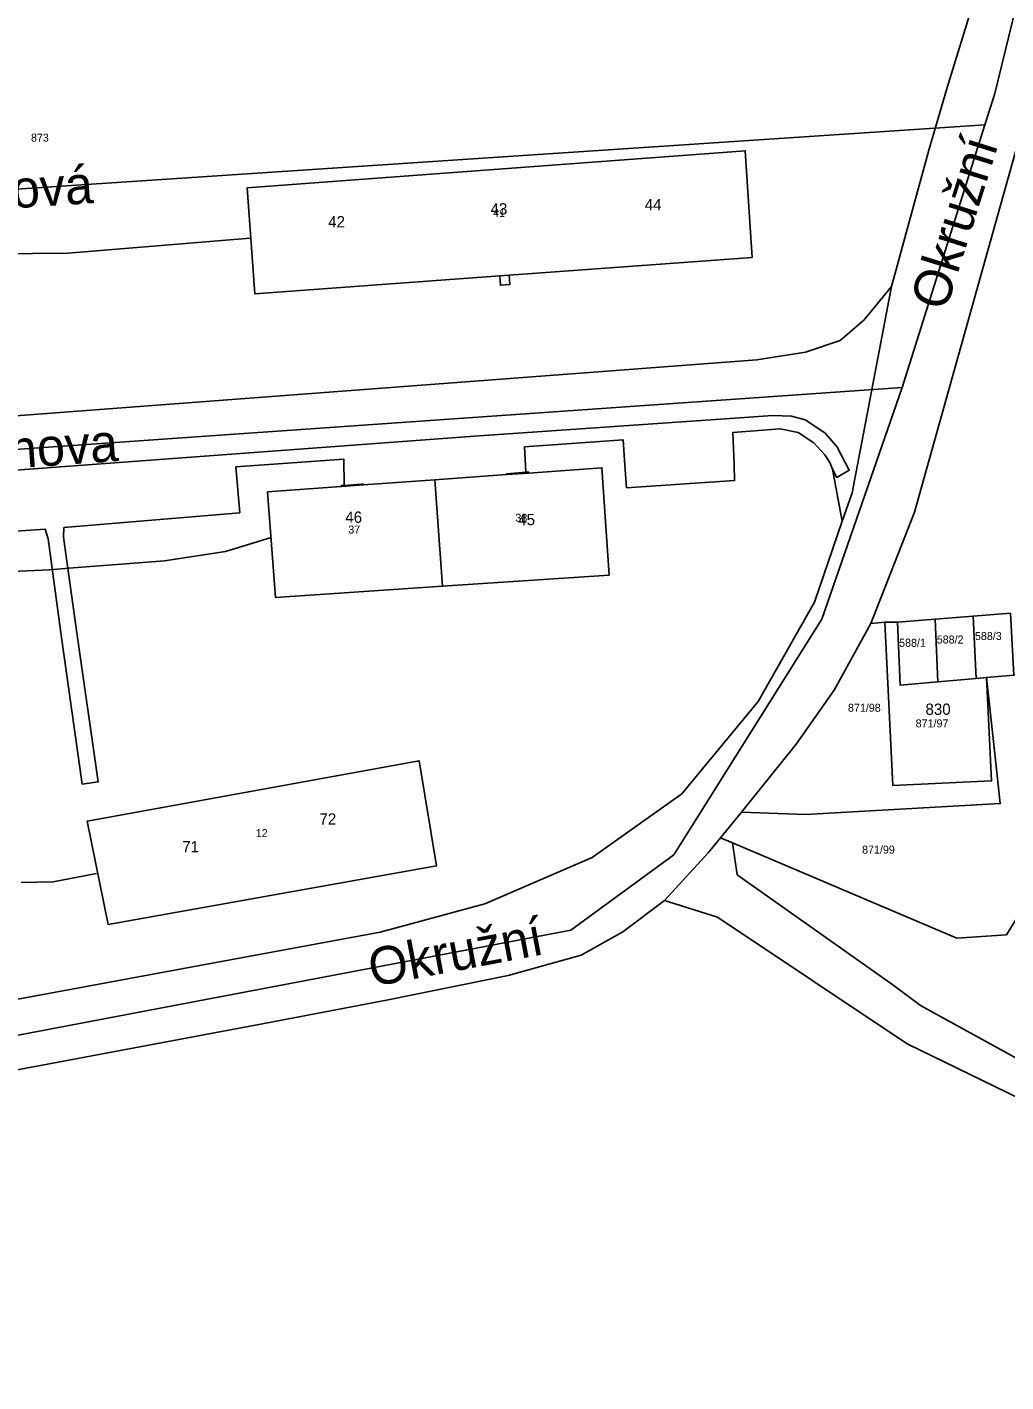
# Model space of a CAD drawing. Extents: x -873642 to -872917, y -1012962 to -1012567.
# Drawn here: x -873173.4 to -873069.4, y -1012787.3 to -1012643.4 of the extents above; entities that cross this region are included whole.
import ezdxf

# ---------------------------------------------------------------- set-up
doc = ezdxf.new("R2010")
doc.units = 0
for name, color, linetype in [('adresni_misto', 7, 'Continuous'), ('cisla_parcelni_kn', 7, 'Continuous'), ('cislo_domovni', 7, 'Continuous'), ('osy_ulic', 7, 'Continuous'), ('parcely_kn', 7, 'Continuous'), ('stavebni_objekty_bydleni', 7, 'Continuous'), ('stavebni_objekty_ostatni', 7, 'Continuous'), ('TRASY - zamereno', 7, 'Continuous'), ('ulice', 7, 'Continuous')]:
    doc.layers.add(name, color=color, linetype=linetype)

msp = doc.modelspace()

# ---------------------------------------------------------------- linework, layer by layer
at = {"layer": 'adresni_misto'}
for p, q in [((-873123.13, -1012664.19), (-873123.13, -1012664.19)), ((-873106.75, -1012663.75), (-873106.75, -1012663.75)), ((-873140.38, -1012665.56), (-873140.38, -1012665.56)), ((-873138.56, -1012696.94), (-873138.56, -1012696.94)), ((-873120.19, -1012697.19), (-873120.19, -1012697.19)), ((-873076.33, -1012717.34), (-873076.33, -1012717.34)), ((-873141.31, -1012729), (-873141.31, -1012729)), ((-873155.88, -1012731.94), (-873155.88, -1012731.94))]:
    msp.add_line(p, q, dxfattribs=at)
at = {"layer": 'osy_ulic'}
for points in [[(-873411.85, -1012822.53), (-873317.85, -1012788.44), (-873277.23, -1012773.91), (-873252.76, -1012767.01), (-873201.18, -1012755.57), (-873115.6, -1012739.3), (-873104.65, -1012731.3), (-873088.93, -1012706.26), (-873080.41, -1012681.66), (-873071.61, -1012653.78), (-873070.57, -1012650.45), (-873066.08, -1012632.13), (-873063.74, -1012625.63), (-873059.56, -1012597.3)], [(-873071.61, -1012653.78), (-873259.84, -1012666.28), (-873257.79, -1012694.05)], [(-873471.18, -1012707.47), (-873461.09, -1012708.93), (-873257.79, -1012694.05), (-873080.41, -1012681.66)]]:
    msp.add_lwpolyline(points, dxfattribs=at)
at = {"layer": 'parcely_kn'}
for points in [[(-873079.43, -1012607.12), (-873054.9, -1012604.66), (-873052.37, -1012604.41), (-873054.28, -1012608.24), (-873059.76, -1012619.22), (-873058.34, -1012622.19), (-873062.75, -1012637.7), (-873065.7, -1012641.7), (-873065.38, -1012647.07), (-873066.31, -1012649.31), (-873079.09, -1012694.9), (-873083.74, -1012706.73), (-873087.64, -1012713.81), (-873091.65, -1012719.56), (-873097.47, -1012726.79), (-873099.7, -1012729.49), (-873101.03, -1012731.11), (-873105.65, -1012736.17), (-873110.07, -1012739.5), (-873114.5, -1012741.96), (-873122.26, -1012744.11), (-873135.01, -1012746.72), (-873148.18, -1012749.22), (-873185.58, -1012756.25)], [(-873079.43, -1012607.12), (-873054.9, -1012604.66), (-873052.37, -1012604.41), (-873054.28, -1012608.24), (-873059.76, -1012619.22), (-873058.34, -1012622.19), (-873062.75, -1012637.7), (-873065.7, -1012641.7), (-873065.38, -1012647.07), (-873066.31, -1012649.31), (-873079.09, -1012694.9), (-873083.74, -1012706.73), (-873087.64, -1012713.81), (-873091.65, -1012719.56), (-873097.47, -1012726.79), (-873099.7, -1012729.49), (-873101.03, -1012731.11), (-873105.65, -1012736.17), (-873110.07, -1012739.5), (-873114.5, -1012741.96), (-873122.26, -1012744.11), (-873135.01, -1012746.72), (-873148.18, -1012749.22), (-873185.58, -1012756.25)], [(-873320.46, -1012784.28), (-873268.07, -1012767.54), (-873249.92, -1012762.57), (-873226.73, -1012756.94), (-873186.64, -1012748.89), (-873149.68, -1012742.06), (-873135.84, -1012739.52), (-873124.72, -1012736.51), (-873113.32, -1012731.6), (-873103.81, -1012724.84), (-873095.71, -1012715.02), (-873089.72, -1012704.46), (-873086.77, -1012695.86), (-873085.73, -1012692.85), (-873081.52, -1012670.94), (-873077.58, -1012656.47), (-873075.63, -1012649.79), (-873072.81, -1012640.75), (-873068.46, -1012627.76), (-873067.09, -1012621.71)], [(-873320.46, -1012784.28), (-873268.07, -1012767.54), (-873249.92, -1012762.57), (-873226.73, -1012756.94), (-873186.64, -1012748.89), (-873149.68, -1012742.06), (-873135.84, -1012739.52), (-873124.72, -1012736.51), (-873113.32, -1012731.6), (-873103.81, -1012724.84), (-873095.71, -1012715.02), (-873089.72, -1012704.46), (-873086.77, -1012695.86), (-873085.73, -1012692.85), (-873081.52, -1012670.94), (-873077.58, -1012656.47), (-873075.63, -1012649.79), (-873072.81, -1012640.75), (-873068.46, -1012627.76), (-873067.09, -1012621.71)], [(-873067.09, -1012621.71), (-873068.46, -1012627.76), (-873072.81, -1012640.75), (-873075.63, -1012649.79), (-873077.58, -1012656.47), (-873081.52, -1012670.94), (-873084.44, -1012674.48), (-873086.98, -1012676.69), (-873090.68, -1012677.91), (-873095.85, -1012678.72), (-873263.61, -1012691.39)], [(-873067.09, -1012621.71), (-873068.46, -1012627.76), (-873072.81, -1012640.75), (-873075.63, -1012649.79), (-873077.58, -1012656.47), (-873081.52, -1012670.94), (-873084.44, -1012674.48), (-873086.98, -1012676.69), (-873090.68, -1012677.91), (-873095.85, -1012678.72), (-873263.61, -1012691.39)], [(-873068.89, -1012705.62), (-873072.87, -1012705.95), (-873076.91, -1012706.28), (-873080.89, -1012706.61), (-873082.23, -1012706.6), (-873083.74, -1012706.73), (-873079.09, -1012694.9), (-873066.31, -1012649.31)], [(-873068.89, -1012705.62), (-873072.87, -1012705.95), (-873076.91, -1012706.28), (-873080.89, -1012706.61), (-873082.23, -1012706.6), (-873083.74, -1012706.73), (-873079.09, -1012694.9), (-873066.31, -1012649.31)], [(-873263.61, -1012691.39), (-873095.85, -1012678.72), (-873090.68, -1012677.91), (-873086.98, -1012676.69), (-873084.44, -1012674.48), (-873081.52, -1012670.94), (-873085.73, -1012692.85), (-873086.77, -1012695.86), (-873087.8, -1012690.33), (-873087.35, -1012691.21), (-873086.02, -1012690.46), (-873087.36, -1012687.92), (-873088.63, -1012686.48), (-873090.71, -1012685.11), (-873092.16, -1012684.7), (-873094.19, -1012684.63), (-873097.17, -1012684.84), (-873125.83, -1012686.85), (-873192.31, -1012691.74)], [(-873263.61, -1012691.39), (-873095.85, -1012678.72), (-873090.68, -1012677.91), (-873086.98, -1012676.69), (-873084.44, -1012674.48), (-873081.52, -1012670.94), (-873085.73, -1012692.85), (-873086.77, -1012695.86), (-873087.8, -1012690.33), (-873087.35, -1012691.21), (-873086.02, -1012690.46), (-873087.36, -1012687.92), (-873088.63, -1012686.48), (-873090.71, -1012685.11), (-873092.16, -1012684.7), (-873094.19, -1012684.63), (-873097.17, -1012684.84), (-873125.83, -1012686.85), (-873192.31, -1012691.74)], [(-873192.31, -1012691.74), (-873125.83, -1012686.85), (-873097.17, -1012684.84), (-873094.19, -1012684.63), (-873092.16, -1012684.7), (-873090.71, -1012685.11), (-873088.63, -1012686.48), (-873087.36, -1012687.92), (-873086.02, -1012690.46), (-873087.35, -1012691.21), (-873087.8, -1012690.33), (-873088.09, -1012689.62), (-873088.61, -1012688.81), (-873089.78, -1012687.56), (-873091.46, -1012686.44), (-873093.35, -1012686.07), (-873098.39, -1012686.43), (-873098.26, -1012689.84), (-873098.2, -1012691.55), (-873109.68, -1012692.31), (-873109.85, -1012689.9), (-873110.04, -1012687.24), (-873120.52, -1012687.97), (-873120.37, -1012690.67), (-873121.97, -1012690.79), (-873122.43, -1012690.82), (-873122.43, -1012690.92), (-873130.05, -1012691.47), (-873137.64, -1012692.02), (-873137.65, -1012691.92), (-873137.83, -1012691.93), (-873139.68, -1012692.07), (-873139.71, -1012689.29), (-873151.19, -1012690.1), (-873150.77, -1012694.97), (-873169.45, -1012696.55), (-873169.48, -1012697.55), (-873168.1, -1012707.49), (-873165.81, -1012723.57), (-873167.5, -1012723.8), (-873169.77, -1012707.72), (-873171.13, -1012697.75), (-873171.45, -1012696.71), (-873178.09, -1012697.19)], [(-873192.31, -1012691.74), (-873125.83, -1012686.85), (-873097.17, -1012684.84), (-873094.19, -1012684.63), (-873092.16, -1012684.7), (-873090.71, -1012685.11), (-873088.63, -1012686.48), (-873087.36, -1012687.92), (-873086.02, -1012690.46), (-873087.35, -1012691.21), (-873087.8, -1012690.33), (-873088.09, -1012689.62), (-873088.61, -1012688.81), (-873089.78, -1012687.56), (-873091.46, -1012686.44), (-873093.35, -1012686.07), (-873098.39, -1012686.43), (-873098.26, -1012689.84), (-873098.2, -1012691.55), (-873109.68, -1012692.31), (-873109.85, -1012689.9), (-873110.04, -1012687.24), (-873120.52, -1012687.97), (-873120.37, -1012690.67), (-873121.97, -1012690.79), (-873122.43, -1012690.82), (-873122.43, -1012690.92), (-873130.05, -1012691.47), (-873137.64, -1012692.02), (-873137.65, -1012691.92), (-873137.83, -1012691.93), (-873139.68, -1012692.07), (-873139.71, -1012689.29), (-873151.19, -1012690.1), (-873150.77, -1012694.97), (-873169.45, -1012696.55), (-873169.48, -1012697.55), (-873168.1, -1012707.49), (-873165.81, -1012723.57), (-873167.5, -1012723.8), (-873169.77, -1012707.72), (-873171.13, -1012697.75), (-873171.45, -1012696.71), (-873178.09, -1012697.19)], [(-873178.09, -1012697.19), (-873171.45, -1012696.71), (-873171.13, -1012697.75), (-873169.77, -1012707.72), (-873167.5, -1012723.8), (-873165.81, -1012723.57), (-873168.1, -1012707.49), (-873169.48, -1012697.55), (-873169.45, -1012696.55), (-873150.77, -1012694.97), (-873151.19, -1012690.1), (-873139.71, -1012689.29), (-873139.68, -1012692.07), (-873139.99, -1012692.09), (-873139.99, -1012692.19), (-873147.82, -1012692.75), (-873146.96, -1012703.97), (-873129.24, -1012702.78), (-873111.54, -1012701.6), (-873112.3, -1012690.19), (-873120.08, -1012690.75), (-873120.09, -1012690.65), (-873120.37, -1012690.67), (-873120.52, -1012687.97), (-873110.04, -1012687.24), (-873109.85, -1012689.9), (-873109.68, -1012692.31), (-873098.2, -1012691.55), (-873098.26, -1012689.84), (-873098.39, -1012686.43), (-873093.35, -1012686.07), (-873091.46, -1012686.44), (-873089.78, -1012687.56), (-873088.61, -1012688.81), (-873088.09, -1012689.62), (-873087.8, -1012690.33), (-873086.77, -1012695.86), (-873089.72, -1012704.46), (-873095.71, -1012715.02), (-873103.81, -1012724.84), (-873113.32, -1012731.6), (-873124.72, -1012736.51), (-873135.84, -1012739.52), (-873149.68, -1012742.06), (-873186.64, -1012748.89)], [(-873178.09, -1012697.19), (-873171.45, -1012696.71), (-873171.13, -1012697.75), (-873169.77, -1012707.72), (-873167.5, -1012723.8), (-873165.81, -1012723.57), (-873168.1, -1012707.49), (-873169.48, -1012697.55), (-873169.45, -1012696.55), (-873150.77, -1012694.97), (-873151.19, -1012690.1), (-873139.71, -1012689.29), (-873139.68, -1012692.07), (-873139.99, -1012692.09), (-873139.99, -1012692.19), (-873147.82, -1012692.75), (-873146.96, -1012703.97), (-873129.24, -1012702.78), (-873111.54, -1012701.6), (-873112.3, -1012690.19), (-873120.08, -1012690.75), (-873120.09, -1012690.65), (-873120.37, -1012690.67), (-873120.52, -1012687.97), (-873110.04, -1012687.24), (-873109.85, -1012689.9), (-873109.68, -1012692.31), (-873098.2, -1012691.55), (-873098.26, -1012689.84), (-873098.39, -1012686.43), (-873093.35, -1012686.07), (-873091.46, -1012686.44), (-873089.78, -1012687.56), (-873088.61, -1012688.81), (-873088.09, -1012689.62), (-873087.8, -1012690.33), (-873086.77, -1012695.86), (-873089.72, -1012704.46), (-873095.71, -1012715.02), (-873103.81, -1012724.84), (-873113.32, -1012731.6), (-873124.72, -1012736.51), (-873135.84, -1012739.52), (-873149.68, -1012742.06), (-873186.64, -1012748.89)], [(-872958.67, -1012787.72), (-872975.04, -1012782.47), (-872991.42, -1012777.17), (-873018.29, -1012770.78), (-873034.35, -1012766.02), (-873054.3, -1012761.9), (-873065.25, -1012758.5), (-873079.89, -1012751.4), (-873100.03, -1012737.92), (-873105.65, -1012736.17), (-873101.03, -1012731.11), (-873099.7, -1012729.49), (-873098.43, -1012730.03), (-873097.94, -1012733.42), (-873081.4, -1012745.11), (-873078.44, -1012747.33), (-873067.46, -1012753.38), (-873059.91, -1012755.24), (-873032.7, -1012762.55), (-873015.14, -1012768.05), (-872991.17, -1012772.9), (-872969.11, -1012779.09), (-872954.48, -1012785.31), (-872943.22, -1012794.81)], [(-872958.67, -1012787.72), (-872975.04, -1012782.47), (-872991.42, -1012777.17), (-873018.29, -1012770.78), (-873034.35, -1012766.02), (-873054.3, -1012761.9), (-873065.25, -1012758.5), (-873079.89, -1012751.4), (-873100.03, -1012737.92), (-873105.65, -1012736.17), (-873101.03, -1012731.11), (-873099.7, -1012729.49), (-873098.43, -1012730.03), (-873097.94, -1012733.42), (-873081.4, -1012745.11), (-873078.44, -1012747.33), (-873067.46, -1012753.38), (-873059.91, -1012755.24), (-873032.7, -1012762.55), (-873015.14, -1012768.05), (-872991.17, -1012772.9), (-872969.11, -1012779.09), (-872954.48, -1012785.31), (-872943.22, -1012794.81)], [(-873067.46, -1012753.38), (-873078.44, -1012747.33), (-873081.4, -1012745.11), (-873097.94, -1012733.42), (-873098.43, -1012730.03), (-873074.59, -1012740.17), (-873069.33, -1012739.79)], [(-873067.46, -1012753.38), (-873078.44, -1012747.33), (-873081.4, -1012745.11), (-873097.94, -1012733.42), (-873098.43, -1012730.03), (-873074.59, -1012740.17), (-873069.33, -1012739.79)], [(-873185.58, -1012756.25), (-873148.18, -1012749.22), (-873135.01, -1012746.72), (-873122.26, -1012744.11), (-873114.5, -1012741.96), (-873110.07, -1012739.5), (-873105.65, -1012736.17), (-873100.03, -1012737.92), (-873079.89, -1012751.4), (-873065.25, -1012758.5), (-873054.3, -1012761.9), (-873034.35, -1012766.02), (-873018.29, -1012770.78), (-872991.42, -1012777.17), (-872975.04, -1012782.47), (-872958.67, -1012787.72)], [(-873185.58, -1012756.25), (-873148.18, -1012749.22), (-873135.01, -1012746.72), (-873122.26, -1012744.11), (-873114.5, -1012741.96), (-873110.07, -1012739.5), (-873105.65, -1012736.17), (-873100.03, -1012737.92), (-873079.89, -1012751.4), (-873065.25, -1012758.5), (-873054.3, -1012761.9), (-873034.35, -1012766.02), (-873018.29, -1012770.78), (-872991.42, -1012777.17), (-872975.04, -1012782.47), (-872958.67, -1012787.72)]]:
    msp.add_lwpolyline(points, dxfattribs=at)
for points in [[(-873150, -1012660.46), (-873149.18, -1012671.71), (-873123.16, -1012669.81), (-873123.09, -1012670.81), (-873122.09, -1012670.73), (-873122.17, -1012669.74), (-873096.35, -1012667.85), (-873097.08, -1012656.52)], [(-873150, -1012660.46), (-873097.08, -1012656.52), (-873096.35, -1012667.85), (-873122.17, -1012669.74), (-873122.09, -1012670.73), (-873123.09, -1012670.81), (-873123.16, -1012669.81), (-873149.18, -1012671.71)], [(-873150, -1012660.46), (-873149.18, -1012671.71), (-873123.16, -1012669.81), (-873123.09, -1012670.81), (-873122.09, -1012670.73), (-873122.17, -1012669.74), (-873096.35, -1012667.85), (-873097.08, -1012656.52)], [(-873150, -1012660.46), (-873097.08, -1012656.52), (-873096.35, -1012667.85), (-873122.17, -1012669.74), (-873122.09, -1012670.73), (-873123.09, -1012670.81), (-873123.16, -1012669.81), (-873149.18, -1012671.71)], [(-873120.08, -1012690.75), (-873112.3, -1012690.19), (-873111.54, -1012701.6), (-873129.24, -1012702.78), (-873130.05, -1012691.47), (-873122.43, -1012690.92), (-873122.43, -1012690.82), (-873121.97, -1012690.79), (-873120.37, -1012690.67), (-873120.09, -1012690.65)], [(-873120.08, -1012690.75), (-873112.3, -1012690.19), (-873111.54, -1012701.6), (-873129.24, -1012702.78), (-873130.05, -1012691.47), (-873122.43, -1012690.92), (-873122.43, -1012690.82), (-873121.97, -1012690.79), (-873120.37, -1012690.67), (-873120.09, -1012690.65)], [(-873130.05, -1012691.47), (-873129.24, -1012702.78), (-873146.96, -1012703.97), (-873147.82, -1012692.75), (-873139.99, -1012692.19), (-873139.99, -1012692.09), (-873139.68, -1012692.07), (-873137.83, -1012691.93), (-873137.65, -1012691.92), (-873137.64, -1012692.02)], [(-873130.05, -1012691.47), (-873129.24, -1012702.78), (-873146.96, -1012703.97), (-873147.82, -1012692.75), (-873139.99, -1012692.19), (-873139.99, -1012692.09), (-873139.68, -1012692.07), (-873137.83, -1012691.93), (-873137.65, -1012691.92), (-873137.64, -1012692.02)], [(-873082.23, -1012706.6), (-873081.39, -1012723.96), (-873070.91, -1012723.45), (-873071.45, -1012712.46), (-873070.53, -1012720.91), (-873069.98, -1012725.86), (-873090.67, -1012727.04), (-873097.47, -1012726.79), (-873091.65, -1012719.56), (-873087.64, -1012713.81), (-873083.74, -1012706.73)], [(-873082.23, -1012706.6), (-873081.39, -1012723.96), (-873070.91, -1012723.45), (-873071.45, -1012712.46), (-873070.53, -1012720.91), (-873069.98, -1012725.86), (-873090.67, -1012727.04), (-873097.47, -1012726.79), (-873091.65, -1012719.56), (-873087.64, -1012713.81), (-873083.74, -1012706.73)], [(-873080.6, -1012713.3), (-873076.6, -1012712.94), (-873072.55, -1012712.57), (-873071.45, -1012712.46), (-873070.91, -1012723.45), (-873081.39, -1012723.96), (-873082.23, -1012706.6), (-873080.89, -1012706.61)], [(-873080.6, -1012713.3), (-873076.6, -1012712.94), (-873072.55, -1012712.57), (-873071.45, -1012712.46), (-873070.91, -1012723.45), (-873081.39, -1012723.96), (-873082.23, -1012706.6), (-873080.89, -1012706.61)], [(-873076.91, -1012706.28), (-873076.6, -1012712.94), (-873080.6, -1012713.3), (-873080.89, -1012706.61)], [(-873076.91, -1012706.28), (-873076.6, -1012712.94), (-873080.6, -1012713.3), (-873080.89, -1012706.61)], [(-873072.87, -1012705.95), (-873072.55, -1012712.57), (-873076.6, -1012712.94), (-873076.91, -1012706.28)], [(-873072.87, -1012705.95), (-873072.55, -1012712.57), (-873076.6, -1012712.94), (-873076.91, -1012706.28)], [(-873068.89, -1012705.62), (-873068.55, -1012712.21), (-873071.45, -1012712.46), (-873072.55, -1012712.57), (-873072.87, -1012705.95)], [(-873068.89, -1012705.62), (-873068.55, -1012712.21), (-873071.45, -1012712.46), (-873072.55, -1012712.57), (-873072.87, -1012705.95)], [(-873071.45, -1012712.46), (-873068.55, -1012712.21), (-873066.38, -1012712.05), (-873064.82, -1012732.54), (-873065.48, -1012733.61), (-873069.33, -1012739.79), (-873074.59, -1012740.17), (-873098.43, -1012730.03), (-873099.7, -1012729.49), (-873097.47, -1012726.79), (-873090.67, -1012727.04), (-873069.98, -1012725.86), (-873070.53, -1012720.91)], [(-873071.45, -1012712.46), (-873068.55, -1012712.21), (-873066.38, -1012712.05), (-873064.82, -1012732.54), (-873065.48, -1012733.61), (-873069.33, -1012739.79), (-873074.59, -1012740.17), (-873098.43, -1012730.03), (-873099.7, -1012729.49), (-873097.47, -1012726.79), (-873090.67, -1012727.04), (-873069.98, -1012725.86), (-873070.53, -1012720.91)], [(-873166.97, -1012727.73), (-873131.73, -1012721.31), (-873129.86, -1012732.48), (-873164.75, -1012738.72)], [(-873129.86, -1012732.48), (-873131.73, -1012721.31), (-873166.97, -1012727.73), (-873164.75, -1012738.72)], [(-873166.97, -1012727.73), (-873131.73, -1012721.31), (-873129.86, -1012732.48), (-873164.75, -1012738.72)], [(-873129.86, -1012732.48), (-873131.73, -1012721.31), (-873166.97, -1012727.73), (-873164.75, -1012738.72)]]:
    msp.add_lwpolyline(points, close=True, dxfattribs=at)
at = {"layer": 'stavebni_objekty_bydleni'}
for points in [[(-873149.18, -1012671.71), (-873150, -1012660.46), (-873097.08, -1012656.52), (-873096.35, -1012667.85), (-873122.17, -1012669.74), (-873123.16, -1012669.81)], [(-873122.43, -1012690.92), (-873120.08, -1012690.75), (-873112.3, -1012690.19), (-873111.54, -1012701.6), (-873129.24, -1012702.78), (-873146.96, -1012703.97), (-873147.82, -1012692.75), (-873139.99, -1012692.19), (-873137.64, -1012692.02), (-873130.05, -1012691.47)], [(-873071.45, -1012712.46), (-873070.91, -1012723.45), (-873081.39, -1012723.96), (-873082.23, -1012706.6), (-873080.89, -1012706.61), (-873080.6, -1012713.3), (-873076.6, -1012712.94), (-873072.55, -1012712.57)], [(-873166.97, -1012727.73), (-873131.73, -1012721.31), (-873129.86, -1012732.48), (-873164.75, -1012738.72)]]:
    msp.add_lwpolyline(points, close=True, dxfattribs=at)
at = {"layer": 'stavebni_objekty_ostatni'}
msp.add_lwpolyline([(-873068.89, -1012705.62), (-873068.55, -1012712.21), (-873071.45, -1012712.46), (-873072.55, -1012712.57), (-873072.87, -1012705.95)], close=True, dxfattribs=at)
at = {"layer": 'TRASY - zamereno'}
for p, q in [((-873149.65, -1012665.82), (-873169.01, -1012667.4)), ((-873169.01, -1012667.4), (-873178.06, -1012667.48)), ((-873147.55, -1012697.62), (-873152.29, -1012699.09)), ((-873152.29, -1012699.09), (-873158.76, -1012700.07)), ((-873168.93, -1012700.84), (-873171, -1012701.05)), ((-873158.76, -1012700.07), (-873168.93, -1012700.84)), ((-873171, -1012701.05), (-873177.71, -1012701.33)), ((-873165.98, -1012733.3), (-873170.6, -1012734.17)), ((-873170.6, -1012734.17), (-873174.01, -1012734.26))]:
    msp.add_line(p, q, dxfattribs=at)

# ---------------------------------------------------------------- texts
at = {"layer": 'cisla_parcelni_kn'}
for s, p in [('873', (-873172.95, -1012655.55)), ('873', (-873172.95, -1012655.55)), ('41', (-873123.86, -1012663.55)), ('41', (-873123.86, -1012663.55)), ('38', (-873121.49, -1012695.93)), ('38', (-873121.49, -1012695.93)), ('37', (-873139.24, -1012697.18)), ('37', (-873139.24, -1012697.18)), ('588/2', (-873076.73, -1012708.86)), ('588/2', (-873076.73, -1012708.86)), ('588/3', (-873072.67, -1012708.49)), ('588/3', (-873072.67, -1012708.49)), ('588/1', (-873080.73, -1012709.21)), ('588/1', (-873080.73, -1012709.21)), ('871/98', (-873086.16, -1012716.11)), ('871/98', (-873086.16, -1012716.11)), ('871/97', (-873078.97, -1012717.77)), ('871/97', (-873078.97, -1012717.77)), ('12', (-873149.08, -1012729.43)), ('12', (-873149.08, -1012729.43)), ('871/99', (-873084.66, -1012731.18)), ('871/99', (-873084.66, -1012731.18))]:
    msp.add_text(s, height=0.85, dxfattribs=at).set_placement(p)
at = {"layer": 'cislo_domovni'}
for s, p in [('44', (-873107.75, -1012662.85)), ('43', (-873124.13, -1012663.29)), ('42', (-873141.38, -1012664.66)), ('46', (-873139.56, -1012696.04)), ('45', (-873121.19, -1012696.29)), ('830', (-873077.93, -1012716.44)), ('72', (-873142.31, -1012728.1)), ('71', (-873156.88, -1012731.04))]:
    msp.add_text(s, height=1.2, dxfattribs=at).set_placement(p)
at = {"layer": 'ulice'}
for s, rotation, p in [('Okružní', 72.4823, (-873075.79, -1012673.67)), ('Mírová', 3.7993, (-873182.57, -1012663.15)), ('Gagarinova', 3.9956, (-873191.18, -1012691.4)), ('Okružní', 10.7643, (-873136.68, -1012745.34))]:
    msp.add_text(s, height=4, rotation=rotation, dxfattribs=at).set_placement(p)

doc.saveas('drawing.dxf')
